// Mitsubishi GX Works2 project: MC-8X-14MT-8MTS-F700-FX2N-A   PLC: FX2N/FX2NC

PROGRAM MAIN
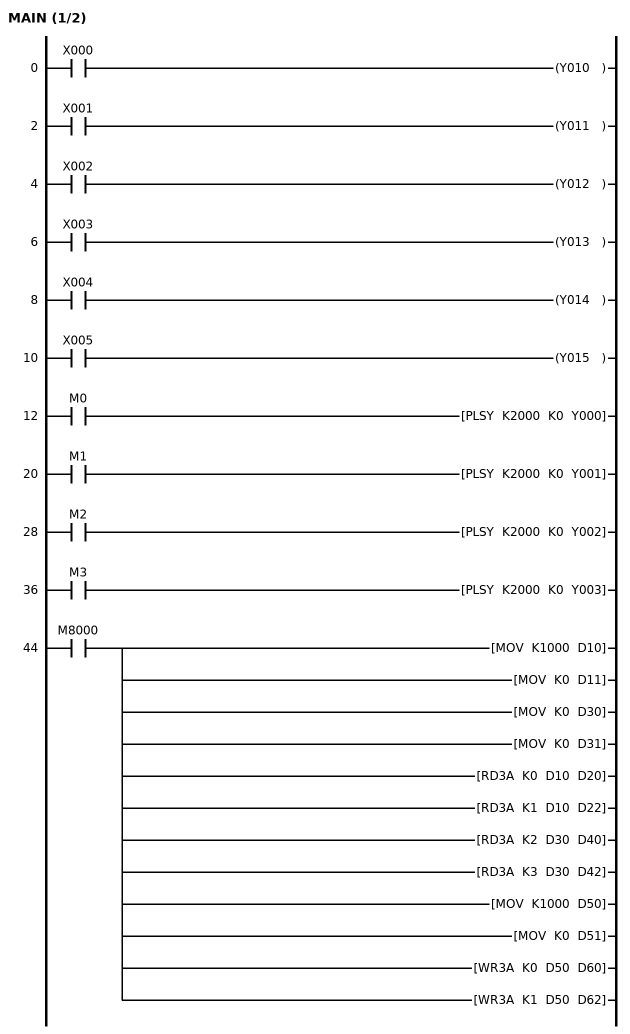
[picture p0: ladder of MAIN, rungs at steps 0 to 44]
0     LD      X000
      OUT     Y010
2     LD      X001
      OUT     Y011
4     LD      X002
      OUT     Y012
6     LD      X003
      OUT     Y013
8     LD      X004
      OUT     Y014
10    LD      X005
      OUT     Y015
12    LD      M0
      PLSY    K2000 K0 Y000
20    LD      M1
      PLSY    K2000 K0 Y001
28    LD      M2
      PLSY    K2000 K0 Y002
36    LD      M3
      PLSY    K2000 K0 Y003
44    LD      M8000
      MOV     K1000 D10
      MOV     K0 D11
      MOV     K0 D30
      MOV     K0 D31
      RD3A    K0 D10 D20
      RD3A    K1 D10 D22
      RD3A    K2 D30 D40
      RD3A    K3 D30 D42
      MOV     K1000 D50
      MOV     K0 D51
      WR3A    K0 D50 D60
      WR3A    K1 D50 D62
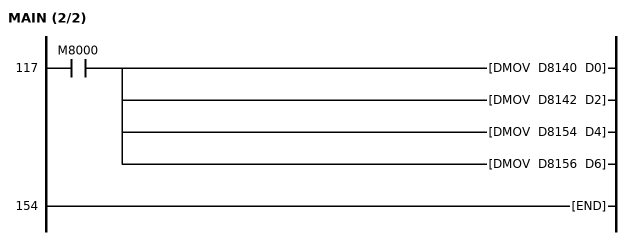
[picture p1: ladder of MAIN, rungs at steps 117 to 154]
117   LD      M8000
      DMOV    D8140 D0
      DMOV    D8142 D2
      DMOV    D8154 D4
      DMOV    D8156 D6
154   END
END_PROGRAM
